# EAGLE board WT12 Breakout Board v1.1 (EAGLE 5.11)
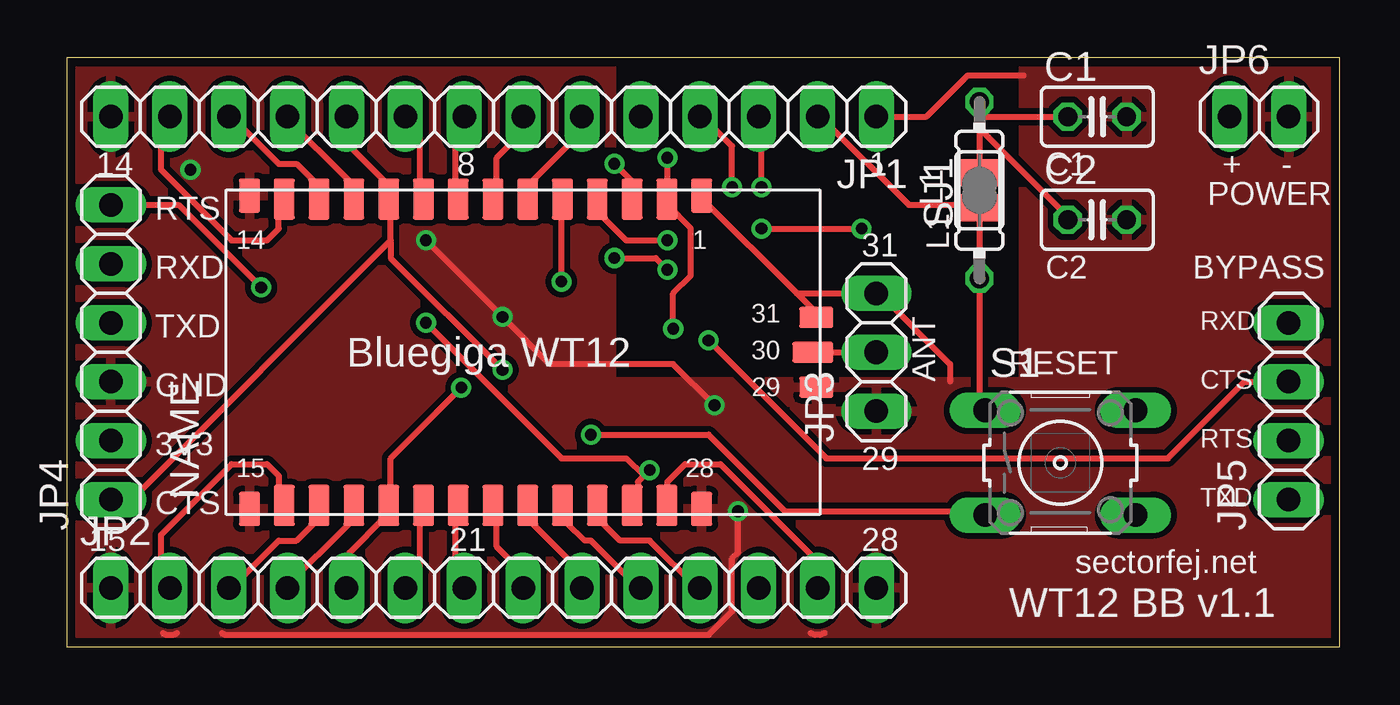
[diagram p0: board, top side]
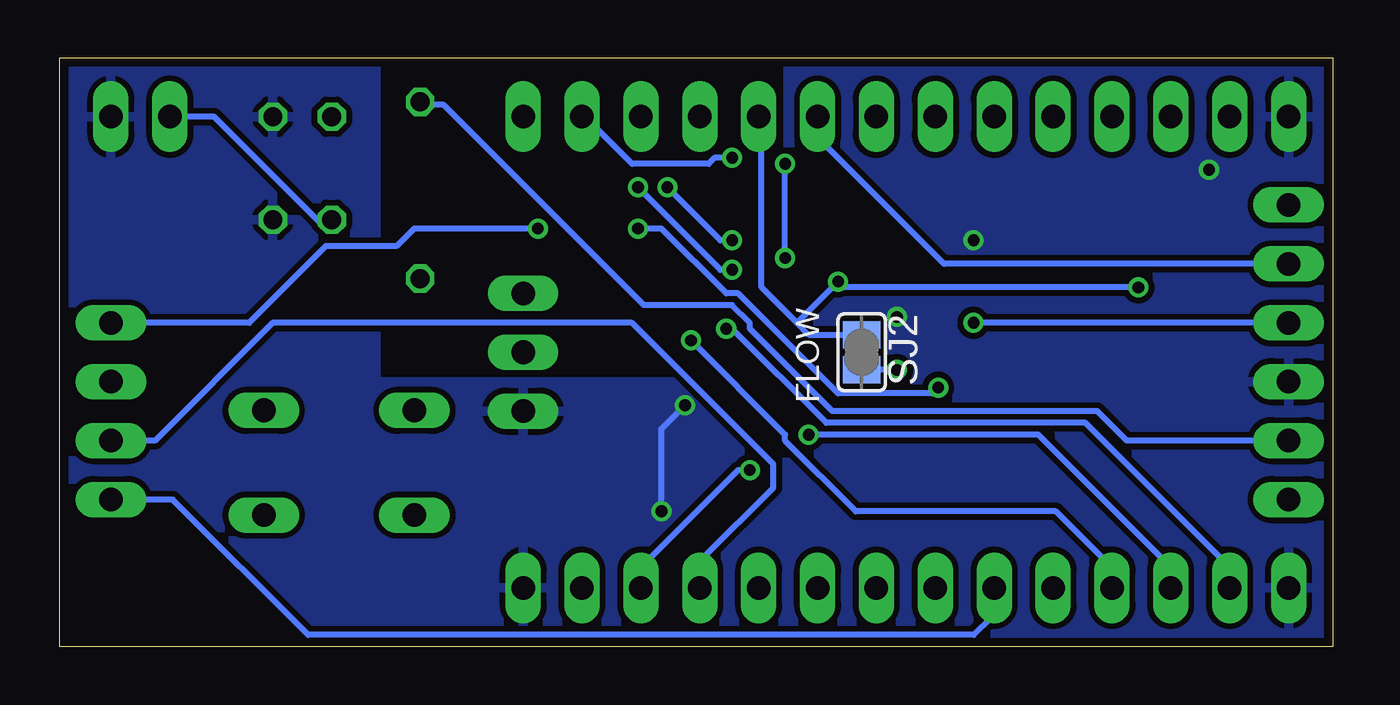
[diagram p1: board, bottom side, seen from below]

Size 54.91 x 25.39 mm. Coordinates in mm from the lower left corner, seen from the top.
Outline: 0,0 54.91,0 54.91,25.39 0,25.39 0,0
Copper layers (1*16): Top 0.0356mm / dielectric 1.5011mm / Bottom 0.0356mm
Design rules "LaenPCBOrder": minimum track width 6mil, minimum drill 13mil, track to track 6mil, track to pad 6mil, pad to pad 6mil, via to via 6mil, smd to smd 6mil, copper to edge 15mil, drill to drill 6mil, minimum pad ring 7mil, minimum via ring 7mil, stop-mask expansion 4mil, vias tented up to drill 0mil, thermal gap 10mil
Net classes: 0 default: width 0.254 mm, drill 0.508 mm, clearance 0.254 mm

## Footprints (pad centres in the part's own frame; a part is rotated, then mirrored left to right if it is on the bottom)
C025-025X050 = drill 0.813 octagon: 1 -1.27,0; 2 1.27,0
1X14 = drill 1.016 long: 1 -16.51,0; 2 -13.97,0; 3 -11.43,0; 4 -8.89,0; 5 -6.35,0; 6 -3.81,0; 7 -1.27,0; 8 1.27,0; 9 3.81,0; 10 6.35,0; 11 8.89,0; 12 11.43,0; 13 13.97,0; 14 16.51,0
1X03 = drill 1.016 long: 1 -2.54,0; 2 0,0; 3 2.54,0
1X06 = drill 1.016 long: 1 -6.35,0; 2 -3.81,0; 3 -1.27,0; 4 1.27,0; 5 3.81,0; 6 6.35,0
1X04 = drill 1.016 long: 1 -3.81,0; 2 -1.27,0; 3 1.27,0; 4 3.81,0
1X02 = drill 1.016 long: 1 -1.27,0; 2 1.27,0
0204/7 = drill 0.813 octagon: 1 -3.81,0; 2 3.81,0
B3F-10XX = drill 1.016 long: 1 -3.251,2.261; 2 3.251,2.261; 3 -3.251,-2.261; 4 3.251,-2.261
SJ = smd 1.168 x 1.6: 1 -0.762,0; 2 0.762,0
WT12 = smd 0.914 x 1.478: GND1 7.7,6.75; GND2 -11.8,6.75; GND3 -11.8,-6.75; GND4 7.7,-6.75 | smd 1.478 x 0.914: GND5 12.65,-1.5; GND6 12.65,1.5 | smd 0.914 x 1.778: MISO 0.2,-6.6; MOSI 1.7,-6.6; NC 6.2,-6.6; NCSB -2.8,-6.6; NCTS -5.8,6.6; NRTS 1.7,6.6; PCMC -8.8,6.6; PCMI -7.3,6.6; PCMO -1.3,6.6; PCMS -10.3,6.6; PIO2 4.7,6.6; PIO3 3.2,6.6; PIO4 -4.3,-6.6; PIO5 3.2,-6.6; PIO6 -7.3,-6.6; PIO7 -5.8,-6.6; RES -8.8,-6.6; RXD 0.2,6.6; SCLK -1.3,-6.6; TXD 4.7,-6.6; USB_D+ -2.8,6.6; USB_D- -4.3,6.6; VDD1 6.2,6.6; VDD2 -10.3,-6.6 | smd 1.778 x 0.914: RF 12.5,0

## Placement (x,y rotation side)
C1  100 nF  [C025-025X050]  44.45,22.86 0 top
C2  NP  [C025-025X050]  44.45,18.41 0 top
JP1  HEADER1  [1X14]  18.41,22.86 180 top
JP2  HEADER2  [1X14]  18.41,2.54 0 top
JP3  ANT  [1X03]  34.92,12.7 90 top
JP4  UART  [1X06]  1.91,12.7 90 top
JP5  BYPASS  [1X04]  52.7,10.16 90 top
JP6  POWER  [1X02]  51.44,22.86 0 top
L1  10 nH  [0204/7]  39.37,19.68 90 top
S1  RESET  [B3F-10XX]  42.86,7.94 0 top
SJ1  PWR  [SJ]  39.37,19.68 90 top
SJ2  FLOW  [SJ]  20.32,12.7 270 bottom
U1  WT12  [WT12]  19.68,12.7 0 top

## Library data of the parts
C1 C2 L1 = resistor
JP1-JP6 = pinhead
S1 = switch-omron; MPN: B3F-1000; OC_FARNELL: 176432; OC_NEWARK: 36M3542
SJ1 SJ2 = jumper
U1 = wt12

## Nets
3V3: C1.1 C2.1 JP4.2 JP6.1 L1.2 SJ1.2
GND: C1.2 C2.2 JP1.1 JP1.14 JP2.1 JP2.14 JP3.1 JP3.3 JP4.3 JP6.2 U1.GND1 U1.GND2 U1.GND3 U1.GND4 U1.GND5 U1.GND6
MISO: JP2.9 U1.MISO
MOSI: JP2.10 U1.MOSI
NC: JP2.13 U1.NC
NCSB: JP2.7 U1.NCSB
NCTS: JP1.10 JP4.1 SJ2.2 U1.NCTS
NRTS: JP1.5 JP4.6 SJ2.1 U1.NRTS
PCMC: JP1.12 U1.PCMC
PCMI: JP1.11 U1.PCMI
PCMO: JP1.7 U1.PCMO
PCMS: JP1.13 U1.PCMS
PIO2: JP1.3 U1.PIO2
PIO3: JP1.4 U1.PIO3
PIO4: JP2.6 JP5.1 U1.PIO4
PIO5: JP2.11 JP5.2 U1.PIO5
PIO6: JP2.4 JP5.3 U1.PIO6
PIO7: JP2.5 JP5.4 U1.PIO7
RES: JP2.3 S1.3 U1.RES
RF: JP3.2 U1.RF
RXD: JP1.6 JP4.5 U1.RXD
SCLK: JP2.8 U1.SCLK
TXD: JP2.12 JP4.4 U1.TXD
USB_D+: JP1.8 U1.USB_D+
USB_D-: JP1.9 U1.USB_D-
VCC: JP1.2 JP2.2 L1.1 S1.1 SJ1.1 U1.VDD1 U1.VDD2

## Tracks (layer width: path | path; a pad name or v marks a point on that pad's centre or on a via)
3V3
  Top 0.254: 39.37,22.86 39.37,22.35 | 39.37,22.35 SJ1.2 | L1.2 39.37,22.86 | 39.37,22.35 43.18,18.54 C2.1 | 39.37,22.86 C1.1
  Bottom 0.254: JP4.2 8.89,8.89 10.16,10.16 21.59,10.16 25.15,13.72 25.15,13.97 25.91,14.73 29.72,14.73 38.35,23.37 39.37,23.37 L1.2 | JP6.1 48.26,22.86 43.69,18.29 43.18,18.29 C2.1
GND  (via drill 0.51)
  Top 0.254: JP1.1 37.08,22.86 38.86,24.64 41.27,24.64 | 31.5,15.24 32.51,14.22 U1.GND6 | 31.5,15.24 27.43,19.3 U1.GND1 | 31.5,15.24 JP3.3 35.05,15.24 38.1,12.19 38.1,11.43 | 4.75,0.58 4.57,0.51 4.32,0.51 4.14,0.58 | v28.96,5.84 28.96,4.06 28.7,3.81 28.7,1.52 27.69,0.51 6.86,0.51 6.68,0.58 | v27.94,10.41 26.16,12.19 20.83,12.19 v18.8,14.22 v15.49,17.53 | 32.08,0.58 32.26,0.51 32.51,0.51 32.69,0.58
  Bottom 0.254: v28.96,5.84 28.96,9.4 v27.94,10.41
  other vias: 5.33,20.57
  pour Bottom: 0,25.4 23.5,25.4 23.5,11.43 41.27,11.43 41.27,25.4 54.93,25.4 54.93,0 0,0
  pour Top: 0,25.4 23.5,25.4 23.5,11.43 41.27,11.43 41.27,25.4 54.93,25.4 54.93,0 0,0
MISO
  Top 0.254: U1.MISO 20.07,6.1 20.07,5.33 22.1,3.3 22.1,2.54 JP2.9
MOSI
  Top 0.254: U1.MOSI 21.59,6.1 21.59,5.33 22.35,4.57 22.61,4.57 24.64,2.54 JP2.10
NC
  Top 0.254: U1.NC 25.91,6.35 25.91,7.11 26.67,7.87 28.19,7.87 32.26,3.81 32.26,2.54 JP2.13
NCSB
  Top 0.254: U1.NCSB 16.76,6.1 16.76,2.79 17.02,2.54 JP2.7
NCTS  (via drill 0.51)
  Top 0.254: v18.8,11.94 13.97,16.76 13.97,17.53 | 13.97,17.53 13.97,19.05 U1.NCTS 13.72,19.3 13.72,20.07 12.19,21.59 12.19,22.86 JP1.10 | 13.97,17.53 2.79,6.35 JP4.1
  Bottom 0.254: v18.8,11.94 SJ2.2
NRTS  (via drill 0.51)
  Top 0.254: v21.34,15.75 21.34,19.05 U1.NRTS | v8.38,15.49 4.83,19.05 JP4.6
  Bottom 0.254: SJ2.1 22.61,13.46 23.11,13.97 | 23.11,13.97 24.64,15.49 24.64,22.86 JP1.5 | 21.59,15.49 23.11,13.97 | v8.38,15.49 21.59,15.49 | 21.59,15.49 v21.34,15.75
PCMC
  Top 0.254: U1.PCMC 10.67,19.3 10.67,20.07 9.91,20.83 9.14,20.83 7.11,22.86 JP1.12
PCMI
  Top 0.254: U1.PCMI 12.19,19.3 12.19,20.07 9.4,22.86 JP1.11
PCMO
  Top 0.254: U1.PCMO 18.54,19.3 18.54,21.08 19.56,22.1 19.56,22.86 JP1.7
PCMS
  Top 0.254: U1.PCMS 9.14,19.05 9.14,18.03 8.64,17.53 7.11,17.53 4.06,20.57 4.06,22.61 4.32,22.86 JP1.13
PIO2  (via drill 0.51)
  Top 0.254: v23.62,20.83 24.38,20.07 U1.PIO2 | v23.62,16.76 25.4,16.76 v25.91,16.26 | v29.97,19.81 29.97,22.86 JP1.3
  Bottom 0.254: v23.62,16.76 v23.62,20.83 | v25.91,16.26 26.42,16.26 v29.97,19.81
PIO3  (via drill 0.51)
  Top 0.254: v25.91,17.53 24.13,17.53 23.11,18.54 23.11,19.05 U1.PIO3 | v28.7,19.81 28.7,21.59 27.43,22.86 JP1.4
  Bottom 0.254: v25.91,17.53 26.42,17.53 v28.7,19.81
PIO4
  Top 0.254: U1.PIO4 15.24,6.1 15.24,3.3 14.48,2.54 JP2.6
  Bottom 0.254: JP5.1 50.04,6.35 44.2,0.51 15.49,0.51 14.73,1.27 14.73,2.54 JP2.6
PIO5
  Top 0.254: U1.PIO5 23.11,6.1 23.11,5.33 23.88,4.57 25.15,4.57 27.18,2.54 JP2.11
  Bottom 0.254: JP5.2 50.8,8.89 45.72,13.97 30.23,13.97 24.13,7.87 24.13,6.86 27.18,3.81 27.18,2.54 JP2.11
PIO6  (via drill 0.51)
  Top 0.254: U1.PIO6 12.19,6.1 12.19,5.33 9.4,2.54 JP2.4 | v27.69,13.21 32.77,8.13 47.5,8.13 50.8,11.43 JP5.3
  Bottom 0.254: v27.69,13.21 23.62,9.14 23.62,8.89 20.57,5.84 11.94,5.84 9.65,3.56 9.65,2.54 JP2.4
PIO7  (via drill 0.51)
  Top 0.254: JP2.5 12.19,2.54 12.19,4.06 13.72,5.59 13.72,6.1 U1.PIO7 13.97,6.35 13.97,8.13 v17.02,11.18 | v29.97,18.03 v34.29,18.03
  Bottom 0.254: v34.29,18.03 39.62,18.03 40.39,17.27 43.43,17.27 46.74,13.97 JP5.4 | v29.97,18.03 28.96,18.03 26.16,15.24 25.65,15.24 21.34,10.92 17.27,10.92 v17.02,11.18
RES  (via drill 0.51)
  Top 0.254: U1.RES 10.67,6.1 10.67,5.33 9.91,4.57 9.14,4.57 7.11,2.54 JP2.3 | v22.61,9.14 27.69,9.14 30.99,5.84 39.37,5.84 S1.3
  Bottom 0.254: v22.61,9.14 12.7,9.14 7.11,3.56 7.11,2.54 JP2.3
RF
  Top 0.254: U1.RF JP3.2
RXD
  Top 0.254: U1.RXD 20.07,19.3 20.07,20.07 22.1,22.1 22.1,22.86 JP1.6
  Bottom 0.254: JP4.5 16.76,16.51 22.1,21.84 22.1,22.86 JP1.6
SCLK
  Top 0.254: U1.SCLK 18.54,6.1 18.54,4.32 19.56,3.3 19.56,2.54 JP2.8
TXD  (via drill 0.51)
  Top 0.254: 24.89,7.37 24.64,7.11 24.64,6.35 U1.TXD | v15.49,13.97 21.34,8.13 24.13,8.13 24.89,7.37 | 24.89,7.37 v25.15,7.62
  Bottom 0.254: v25.15,7.62 25.65,7.62 29.72,3.56 29.72,2.54 JP2.12 | JP4.4 v15.49,13.97
USB_D+
  Top 0.254: U1.USB_D+ 16.76,19.3 16.76,22.61 17.02,22.86 JP1.8
USB_D-
  Top 0.254: U1.USB_D- 15.24,19.3 15.24,22.1 14.48,22.86 JP1.9
VCC  (via drill 0.51)
  Top 0.254: S1.1 39.37,10.41 L1.1 SJ1.1 39.37,19.05 36.32,19.05 32.51,22.86 JP1.2 | U1.VDD2 9.14,6.35 9.14,7.37 8.64,7.87 7.11,7.87 4.06,4.83 4.06,2.79 4.32,2.54 JP2.2 | v25.91,21.08 25.91,19.3 U1.VDD1 25.91,19.05 26.92,18.03 26.92,16 26.16,15.24 v26.16,13.72
  Bottom 0.254: v25.91,21.08 26.67,21.08 26.92,20.83 30.23,20.83 32.26,22.86 JP1.2 | v26.16,13.72 25.91,13.72 21.84,9.65 10.67,9.65 4.57,3.56 4.57,2.54 JP2.2

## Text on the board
tPlace: 14 | 8 | 1 | C1 | + | - | L1 | POWER | RTS | 14 | 1 | 31 | RXD | C2 | BYPASS | 31 | RXD | TXD | Bluegiga WT12 | 30 | RESET | GND | 29 | ANT | CTS | RTS | 3V3 | 29 | 15 | 28 | CTS | TXD | 15 | 21 | 28 | sectorfej.net | WT12 BB v1.1
bPlace: FLOW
